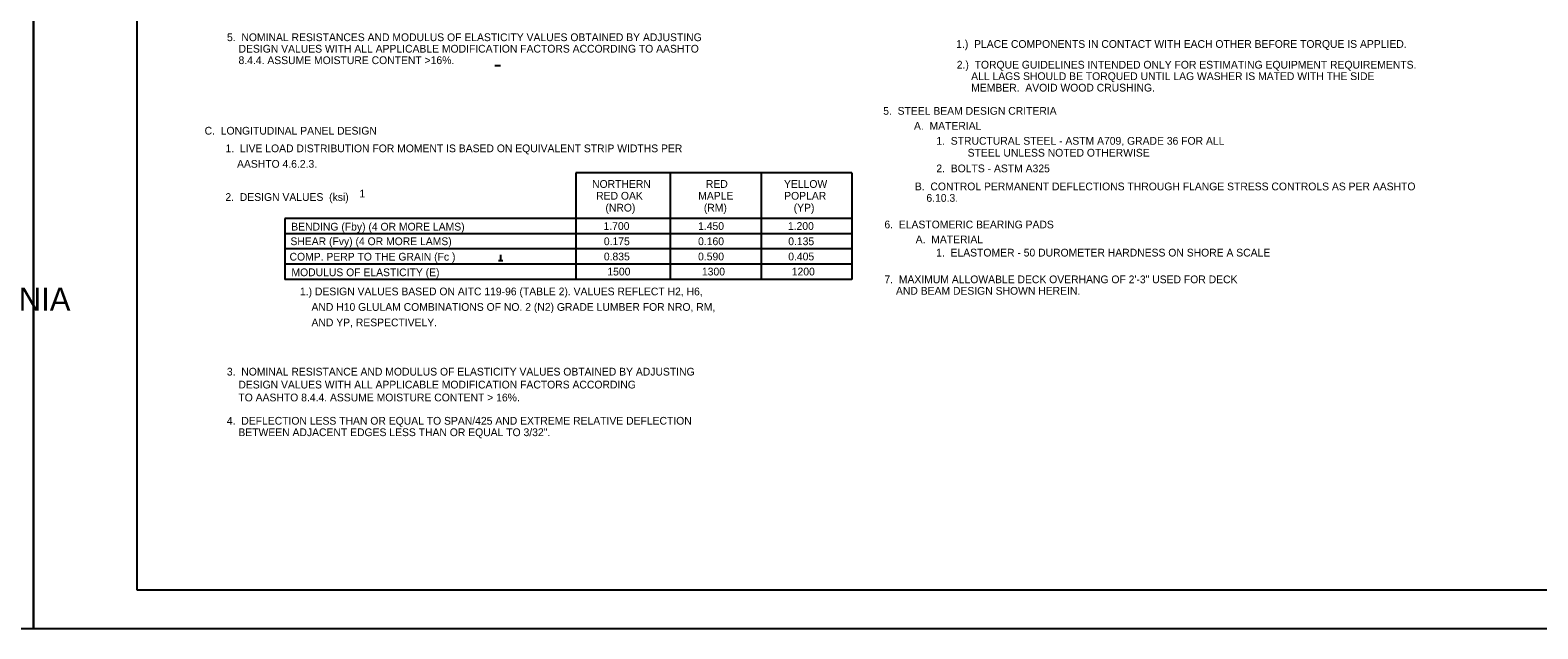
# Model space of a CAD drawing. Extents: x 637594 to 640253, y 297247 to 298435.
# Drawn here: x 639275 to 639859, y 297247 to 297479 of the extents above; entities that cross this region are included whole.
import ezdxf

# ---------------------------------------------------------------- set-up
doc = ezdxf.new("R2010")
doc.units = 0
for name, color, linetype in [('2', 7, 'Continuous'), ('Level 2', 7, 'Continuous'), ('PLT-BNDY', 7, 'Continuous')]:
    doc.layers.add(name, color=color, linetype=linetype)

msp = doc.modelspace()

# ---------------------------------------------------------------- linework, layer by layer
at = {"layer": '2'}
for p, q in [((639316.46, 297262.46), (639316.46, 297826.46)), ((640102.46, 297262.46), (639316.46, 297262.46))]:
    msp.add_line(p, q, dxfattribs=at)
at = {"layer": 'Level 2'}
for p, q in [((639454.91, 297465.56), (639457.16, 297465.56)), ((639593.03, 297424.03), (639486.28, 297424.03)), ((639486.28, 297424.03), (639486.28, 297382.72)), ((639522.73, 297424.03), (639522.73, 297382.72)), ((639557.94, 297424.03), (639557.94, 297382.72)), ((639593.03, 297424.03), (639593.03, 297382.72)), ((639593.03, 297406.33), (639373.64, 297406.33)), ((639373.64, 297406.33), (639373.64, 297382.72)), ((639593.03, 297400.42), (639373.64, 297400.42)), ((639593.03, 297394.52), (639373.64, 297394.52)), ((639457.21, 297390.03), (639457.21, 297392.29)), ((639593.03, 297388.62), (639373.64, 297388.62)), ((639456.39, 297390.03), (639458.04, 297390.03)), ((639593.03, 297382.72), (639373.64, 297382.72))]:
    msp.add_line(p, q, dxfattribs=at)
at = {"layer": 'PLT-BNDY'}
for points in [[(638435.46, 297841.46), (639276.46, 297841.46), (639276.46, 297247.46), (638435.46, 297247.46)], [(639276.46, 297841.46), (640117.46, 297841.46), (640117.46, 297247.46), (639276.46, 297247.46)]]:
    msp.add_lwpolyline(points, close=True, dxfattribs=at)

# ---------------------------------------------------------------- texts
at = {"layer": '2'}
msp.add_text('COMMONWEALTH OF PENNSYLVANIA', height=9, dxfattribs=at).set_placement((639068.71, 297370.58))
at = {"layer": 'Level 2'}
for s, p in [('5.  NOMINAL RESISTANCES AND MODULUS OF ELASTICITY VALUES OBTAINED BY ADJUSTING', (639351.28, 297474.96)), ('    DESIGN VALUES WITH ALL APPLICABLE MODIFICATION FACTORS ACCORDING TO AASHTO', (639351.28, 297470.52)), ('1.)  PLACE COMPONENTS IN CONTACT WITH EACH OTHER BEFORE TORQUE IS APPLIED.', (639633.44, 297472.36)), ('    8.4.4. ASSUME MOISTURE CONTENT >16%.', (639351.28, 297466.07)), ('2.)  TORQUE GUIDELINES INTENDED ONLY FOR ESTIMATING EQUIPMENT REQUIREMENTS.', (639633.66, 297464.33)), ('     ALL LAGS SHOULD BE TORQUED UNTIL LAG WASHER IS MATED WITH THE SIDE', (639633.66, 297459.89)), ('     MEMBER.  AVOID WOOD CRUSHING.', (639633.66, 297455.45)), ('5.  STEEL BEAM DESIGN CRITERIA', (639605.2, 297446.46)), ('C.  LONGITUDINAL PANEL DESIGN', (639342.61, 297438.78)), ('A.  MATERIAL', (639617.1, 297440.66)), ('1.  LIVE LOAD DISTRIBUTION FOR MOMENT IS BASED ON EQUIVALENT STRIP WIDTHS PER', (639350.7, 297431.95)), ('1.  STRUCTURAL STEEL - ASTM A709, GRADE 36 FOR ALL', (639625.76, 297434.86)), ('STEEL UNLESS NOTED OTHERWISE', (639637.87, 297430.26)), ('    AASHTO 4.6.2.3.', (639350.7, 297425.95)), ('2.  BOLTS - ASTM A325', (639625.76, 297424.19)), ('NORTHERN', (639492.55, 297418.17)), ('RED', (639536.58, 297418.17)), ('YELLOW', (639566.81, 297418.17)), ('2.  DESIGN VALUES  (ksi)', (639350.66, 297413.11)), ('1', (639402.48, 297414.44)), ('RED OAK', (639494.12, 297413.59)), ('MAPLE', (639533.62, 297413.59)), ('POPLAR', (639566.88, 297413.59)), ('B.  CONTROL PERMANENT DEFLECTIONS THROUGH FLANGE STRESS CONTROLS AS PER AASHTO', (639617.45, 297417.21)), ('    6.10.3.', (639617.45, 297412.77)), ('(NRO)', (639497.71, 297409)), ('(RM)', (639535.79, 297409)), ('(YP)', (639570.56, 297409)), ('BENDING (Fby) (4 OR MORE LAMS)', (639376.13, 297401.64)), ('1.700', (639496.97, 297401.88)), ('1.450', (639533.56, 297401.88)), ('1.200', (639568.32, 297401.88)), ('6.  ELASTOMERIC BEARING PADS', (639605.67, 297402.48)), ('SHEAR (Fvy) (4 OR MORE LAMS)', (639375.82, 297395.99)), ('0.175', (639497.1, 297395.98)), ('0.160', (639533.56, 297395.98)), ('0.135', (639568.45, 297395.98)), ('A.  MATERIAL', (639617.76, 297396.71)), ('COMP. PERP TO THE GRAIN (Fc )', (639375.48, 297390.01)), ('0.835', (639497.1, 297390.09)), ('0.590', (639533.56, 297390.09)), ('0.405', (639568.45, 297390.09)), ('1.  ELASTOMER - 50 DUROMETER HARDNESS ON SHORE A SCALE', (639625.68, 297391.59)), ('MODULUS OF ELASTICITY (E)', (639376.21, 297383.97)), ('1500', (639498.46, 297384.25)), ('1300', (639535.05, 297384.25)), ('1200', (639569.81, 297384.25)), ('1.) DESIGN VALUES BASED ON AITC 119-96 (TABLE 2). VALUES REFLECT H2, H6,', (639379.51, 297376.56)), ('7.  MAXIMUM ALLOWABLE DECK OVERHANG OF 2\'-3" USED FOR DECK', (639605.67, 297381.24)), ('    AND BEAM DESIGN SHOWN HEREIN.', (639605.67, 297376.8)), ('    AND H10 GLULAM COMBINATIONS OF NO. 2 (N2) GRADE LUMBER FOR NRO, RM,', (639379.51, 297370.56)), ('    AND YP, RESPECTIVELY.', (639379.51, 297364.56)), ('3.  NOMINAL RESISTANCE AND MODULUS OF ELASTICITY VALUES OBTAINED BY ADJUSTING', (639351.22, 297345.51)), ('    DESIGN VALUES WITH ALL APPLICABLE MODIFICATION FACTORS ACCORDING', (639351.22, 297340.51)), ('    TO AASHTO 8.4.4. ASSUME MOISTURE CONTENT > 16%.', (639351.22, 297335.52)), ('4.  DEFLECTION LESS THAN OR EQUAL TO SPAN/425 AND EXTREME RELATIVE DEFLECTION', (639351.22, 297326.5)), ('    BETWEEN ADJACENT EDGES LESS THAN OR EQUAL TO 3/32".', (639351.22, 297322.06))]:
    msp.add_text(s, height=3, dxfattribs=at).set_placement(p)

doc.saveas('drawing.dxf')
